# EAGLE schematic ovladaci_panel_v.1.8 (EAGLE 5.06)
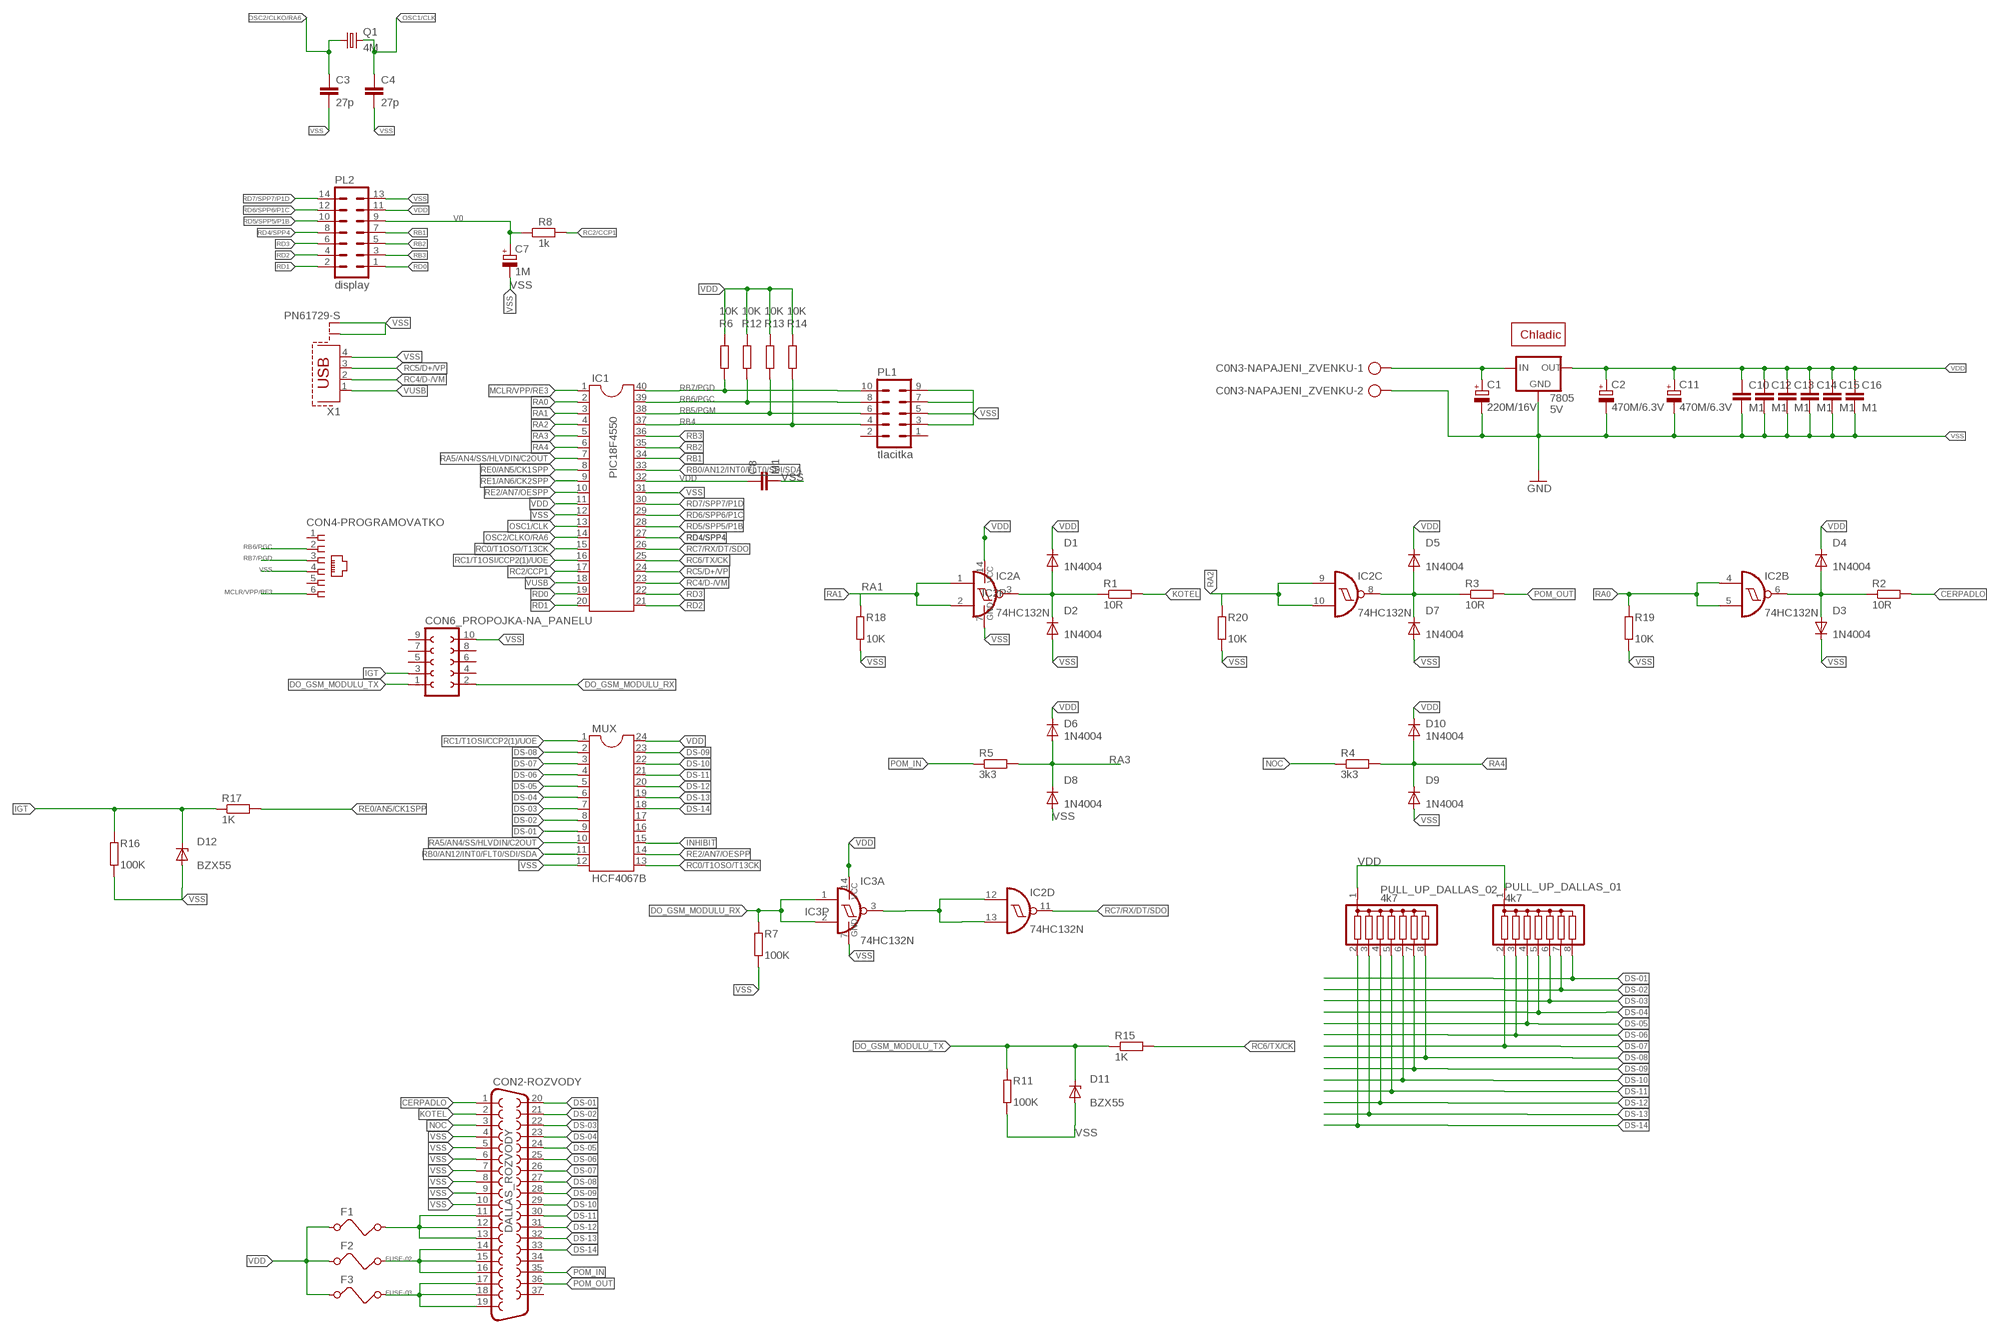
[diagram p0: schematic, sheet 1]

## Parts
7805  5V  78XXL  [78XXL]
C0N3-NAPAJENI_ZVENKU  AK500/2-H  [AK500/2-H]
C1  220M/16V  CPOL-EUE5-13  [E5-13]
C2  470M/6.3V  CPOL-EUE5-13  [E5-13]
C3  27p  C-EU025-025X050  [C025-025X050]
C4  27p  C-EU025-025X050  [C025-025X050]
C7  1M  CPOL-EUE2.5-5  [E2,5-5]
C8  M1  C-EU025-025X050  [C025-025X050]
C10  M1  C-EU025-025X050  [C025-025X050]
C11  470M/6.3V  CPOL-EUE5-13  [E5-13]
C12  M1  C-EU025-025X050  [C025-025X050]
C13  M1  C-EU025-025X050  [C025-025X050]
C14  M1  C-EU025-025X050  [C025-025X050]
C15  M1  C-EU025-025X050  [C025-025X050]
C16  M1  C-EU025-025X050  [C025-025X050]
CON2-ROZVODY  DALLAS_ROZVODY  F37HP  [F37HP]
CON4-PROGRAMOVATKO  520250-3  [520250-3]
CON6_PROPOJKA-NA_PANELU  FE05-2W  [FE05-2W]
D1  1N4004  [DO41-10]
D2  1N4004  [DO41-10]
D3  1N4004  [DO41-10]
D4  1N4004  [DO41-10]
D5  1N4004  [DO41-10]
D6  1N4004  [DO41-10]
D7  1N4004  [DO41-10]
D8  1N4004  [DO41-10]
D9  1N4004  [DO41-10]
D10  1N4004  [DO41-10]
D11  BZX55  [DO35Z10]
D12  BZX55  [DO35Z10]
F1  FUSE  [FUSE]
F2  FUSE  [FUSE]
F3  FUSE  [FUSE]
IC1  PIC18F4550  DIL40  [DIL40]
IC2  74HC132N  [DIL14]
IC3  74HC132N  [DIL14]
MUX  HCF4067B  DIL24-6  [DIL24-6]
PL1  tlacitka  10V  [10V]
PL2  display  14V  [14V]
PULL_UP_DALLAS_01  4k7  G07R  [SIL8]
PULL_UP_DALLAS_02  4k7  G07R  [SIL8]
Q1  4M  CRYSTALHC49S  [HC49/S]
R1  10R  R-EU_0207/10  [0207/10]
R2  10R  R-EU_0207/10  [0207/10]
R3  10R  R-EU_0207/10  [0207/10]
R4  3k3  R-EU_0207/10  [0207/10]
R5  3k3  R-EU_0207/10  [0207/10]
R6  10K  R-EU_0207/10  [0207/10]
R7  100K  R-EU_0207/10  [0207/10]
R8  1k  R-EU_0207/10  [0207/10]
R11  100K  R-EU_0207/10  [0207/10]
R12  10K  R-EU_0207/10  [0207/10]
R13  10K  R-EU_0207/10  [0207/10]
R14  10K  R-EU_0207/10  [0207/10]
R15  1K  R-EU_0207/10  [0207/10]
R16  100K  R-EU_0207/10  [0207/10]
R17  1K  R-EU_0207/10  [0207/10]
R18  10K  R-EU_0207/10  [0207/10]
R19  10K  R-EU_0207/10  [0207/10]
R20  10K  R-EU_0207/10  [0207/10]
U$1  CHLADIC  [CHLADIC]
X1  PN61729-S  [PN61729-S]

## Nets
CERPADLO: CON2-ROZVODY.1 R2.2
CESTA: IC2.12(D:I0) IC2.13(D:I1) IC3.3(A:O)
DO_GSM_MODULU_RX: CON6_PROPOJKA-NA_PANELU.2 IC3.1(A:I0) IC3.2(A:I1) R7.2
DO_GSM_MODULU_TX: CON6_PROPOJKA-NA_PANELU.1 D11.C R11.2 R15.1
DS-01: CON2-ROZVODY.20 MUX.9 PULL_UP_DALLAS_01.8
DS-02: CON2-ROZVODY.21 MUX.8 PULL_UP_DALLAS_01.7
DS-03: CON2-ROZVODY.22 MUX.7 PULL_UP_DALLAS_01.6
DS-04: CON2-ROZVODY.23 MUX.6 PULL_UP_DALLAS_01.5
DS-05: CON2-ROZVODY.24 MUX.5 PULL_UP_DALLAS_01.4
DS-06: CON2-ROZVODY.25 MUX.4 PULL_UP_DALLAS_01.3
DS-07: CON2-ROZVODY.26 MUX.3 PULL_UP_DALLAS_01.2
DS-08: CON2-ROZVODY.27 MUX.2 PULL_UP_DALLAS_02.8
DS-09: CON2-ROZVODY.28 MUX.23 PULL_UP_DALLAS_02.7
DS-10: CON2-ROZVODY.29 MUX.22 PULL_UP_DALLAS_02.6
DS-11: CON2-ROZVODY.30 MUX.21 PULL_UP_DALLAS_02.5
DS-12: CON2-ROZVODY.31 MUX.20 PULL_UP_DALLAS_02.4
DS-13: CON2-ROZVODY.32 MUX.19 PULL_UP_DALLAS_02.3
DS-14: CON2-ROZVODY.33 MUX.18 PULL_UP_DALLAS_02.2
FUSE-02: CON2-ROZVODY.14 CON2-ROZVODY.15 CON2-ROZVODY.16 F2.2
FUSE-03: CON2-ROZVODY.17 CON2-ROZVODY.18 CON2-ROZVODY.19 F3.2
IGT: CON6_PROPOJKA-NA_PANELU.3 D12.C R16.2 R17.1
INHIBIT: MUX.15
KOTEL: CON2-ROZVODY.2 R1.2
MCLR/VPP/RE3: CON4-PROGRAMOVATKO.6 IC1.1
N$1: 7805.IN C0N3-NAPAJENI_ZVENKU.1 C1.+
N$2: D1.A D2.C IC2.3(A:O) R1.1
N$5: D3.A D4.A IC2.6(B:O) R2.1
N$6: D5.A D7.C IC2.8(C:O) R3.1
N$10: CON2-ROZVODY.11 CON2-ROZVODY.12 CON2-ROZVODY.13 F1.2
NOC: CON2-ROZVODY.3 R4.1
OSC1/CLK: C4.1 IC1.13 Q1.2
OSC2/CLKO/RA6: C3.1 IC1.14 Q1.1
POM_IN: CON2-ROZVODY.35 R5.1
POM_OUT: CON2-ROZVODY.36 R3.2
RA0: IC1.2 IC2.4(B:I0) IC2.5(B:I1) R19.2
RA1: IC1.3 IC2.1(A:I0) IC2.2(A:I1) R18.2
RA2: IC1.4 IC2.9(C:I0) IC2.10(C:I1) R20.2
RA3: D6.A D8.C IC1.5 R5.2
RA4: D9.C D10.A IC1.6 R4.2
RA5/AN4/SS/HLVDIN/C2OUT: IC1.7 MUX.10
RB0/AN12/INT0/FLT0/SDI/SDA: IC1.33 MUX.11
RB1: IC1.34 PL2.7
RB2: IC1.35 PL2.5
RB3: IC1.36 PL2.3
RB4: IC1.37 PL1.4 R14.2
RB5/PGM: IC1.38 PL1.6 R13.2
RB6/PGC: CON4-PROGRAMOVATKO.2 IC1.39 PL1.8 R12.2
RB7/PGD: CON4-PROGRAMOVATKO.3 IC1.40 PL1.10 R6.2
RC0/T1OSO/T13CK: IC1.15 MUX.13
RC1/T1OSI/CCP2(1)/UOE: IC1.16 MUX.1
RC2/CCP1: IC1.17 R8.2
RC4/D-/VM: IC1.23 X1.2
RC5/D+/VP: IC1.24 X1.3
RC6/TX/CK: IC1.25 R15.2
RC7/RX/DT/SDO: IC1.26 IC2.11(D:O)
RD0: IC1.19 PL2.1
RD1: IC1.20 PL2.2
RD2: IC1.21 PL2.4
RD3: IC1.22 PL2.6
RD4/SPP4: IC1.27 PL2.8
RD5/SPP5/P1B: IC1.28 PL2.10
RD6/SPP6/P1C: IC1.29 PL2.12
RD7/SPP7/P1D: IC1.30 PL2.14
RE0/AN5/CK1SPP: IC1.8 R17.2
RE1/AN6/CK2SPP: IC1.9
RE2/AN7/OESPP: IC1.10 MUX.14
V0: C7.+ PL2.9 R8.1
VDD: 7805.OUT C2.+ C8.1 C10.1 C11.+ C12.1 C13.1 C14.1 C15.1 C16.1 D1.C D4.C D5.C D6.C D10.C F1.1 F2.1 F3.1 IC1.11 IC1.32 IC2.14(P:VCC) IC3.14(P:VCC) MUX.24 PL2.11 PULL_UP_DALLAS_01.1 PULL_UP_DALLAS_02.1 R6.1 R12.1 R13.1 R14.1
VSS: 7805.GND C0N3-NAPAJENI_ZVENKU.2 C1.- C2.- C3.2 C4.2 C7.- C8.2 C10.2 C11.- C12.2 C13.2 C14.2 C15.2 C16.2 CON2-ROZVODY.4 CON2-ROZVODY.5 CON2-ROZVODY.6 CON2-ROZVODY.7 CON2-ROZVODY.8 CON2-ROZVODY.9 CON2-ROZVODY.10 CON4-PROGRAMOVATKO.4 CON6_PROPOJKA-NA_PANELU.10 D2.A D3.C D7.A D8.A D9.A D11.A D12.A IC1.12 IC1.31 IC2.7(P:GND) IC3.7(P:GND) MUX.12 PL1.3 PL1.5 PL1.7 PL1.9 PL2.13 R7.1 R11.1 R16.1 R18.1 R19.1 R20.1 X1.4 X1.S1 X1.S2 ; supply symbol labelled GND
VUSB: IC1.18 X1.1
Unconnected: CON2-ROZVODY.34 CON2-ROZVODY.37 CON4-PROGRAMOVATKO.1 CON4-PROGRAMOVATKO.5 CON6_PROPOJKA-NA_PANELU.4 CON6_PROPOJKA-NA_PANELU.5 CON6_PROPOJKA-NA_PANELU.6 CON6_PROPOJKA-NA_PANELU.7 CON6_PROPOJKA-NA_PANELU.8 CON6_PROPOJKA-NA_PANELU.9 IC3.4(B:I0) IC3.5(B:I1) IC3.6(B:O) IC3.8(C:O) IC3.9(C:I0) IC3.10(C:I1) IC3.11(D:O) IC3.12(D:I0) IC3.13(D:I1) MUX.16 MUX.17 PL1.1 PL1.2

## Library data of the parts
7805 = v-reg:78XXL: VOLTAGE REGULATOR
C0N3-NAPAJENI_ZVENKU = con-ptr500:AK500/2-H: CONNECTOR
C1 C2 C7 C11 = rcl:CPOL-EU: POLARIZED CAPACITOR, European symbol
C3 C4 C8 C10 C12-C16 = rcl:C-EU: CAPACITOR, European symbol
CON2-ROZVODY = con-subd:F37: SUB-D
CON4-PROGRAMOVATKO = con-amp:520250-3: AMP connector
CON6_PROPOJKA-NA_PANELU = con-lsta:FE05-2W: FEMALE HEADER
D1-D10 = diode:1N4004: DIODE
D11 D12 = diode:BZX55: Z DIODE
F1-F3 = special:FUSE: FUSE
IC1 = ic-package:DIL40: Dual In Line pic
IC2 IC3 = 74xx-eu:74*132: Quad 2-input NAND schmitt trigger
MUX = ic-package:DIL24: Dual In Line
PL1 = con-harting-v:10V: CONNECTOR
PL2 = con-harting-v:14V: CONNECTOR
PULL_UP_DALLAS_01 PULL_UP_DALLAS_02 = resistor-sil:G07R: SIL RESISTOR
Q1 = crystal:CRYSTAL: CRYSTAL
R1-R8 R11-R20 = rcl:R-EU_: RESISTOR, European symbol
U$1 = chladic:CHLADIC: chadic
X1 = con-berg:PN61729-S: BERG USB connector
